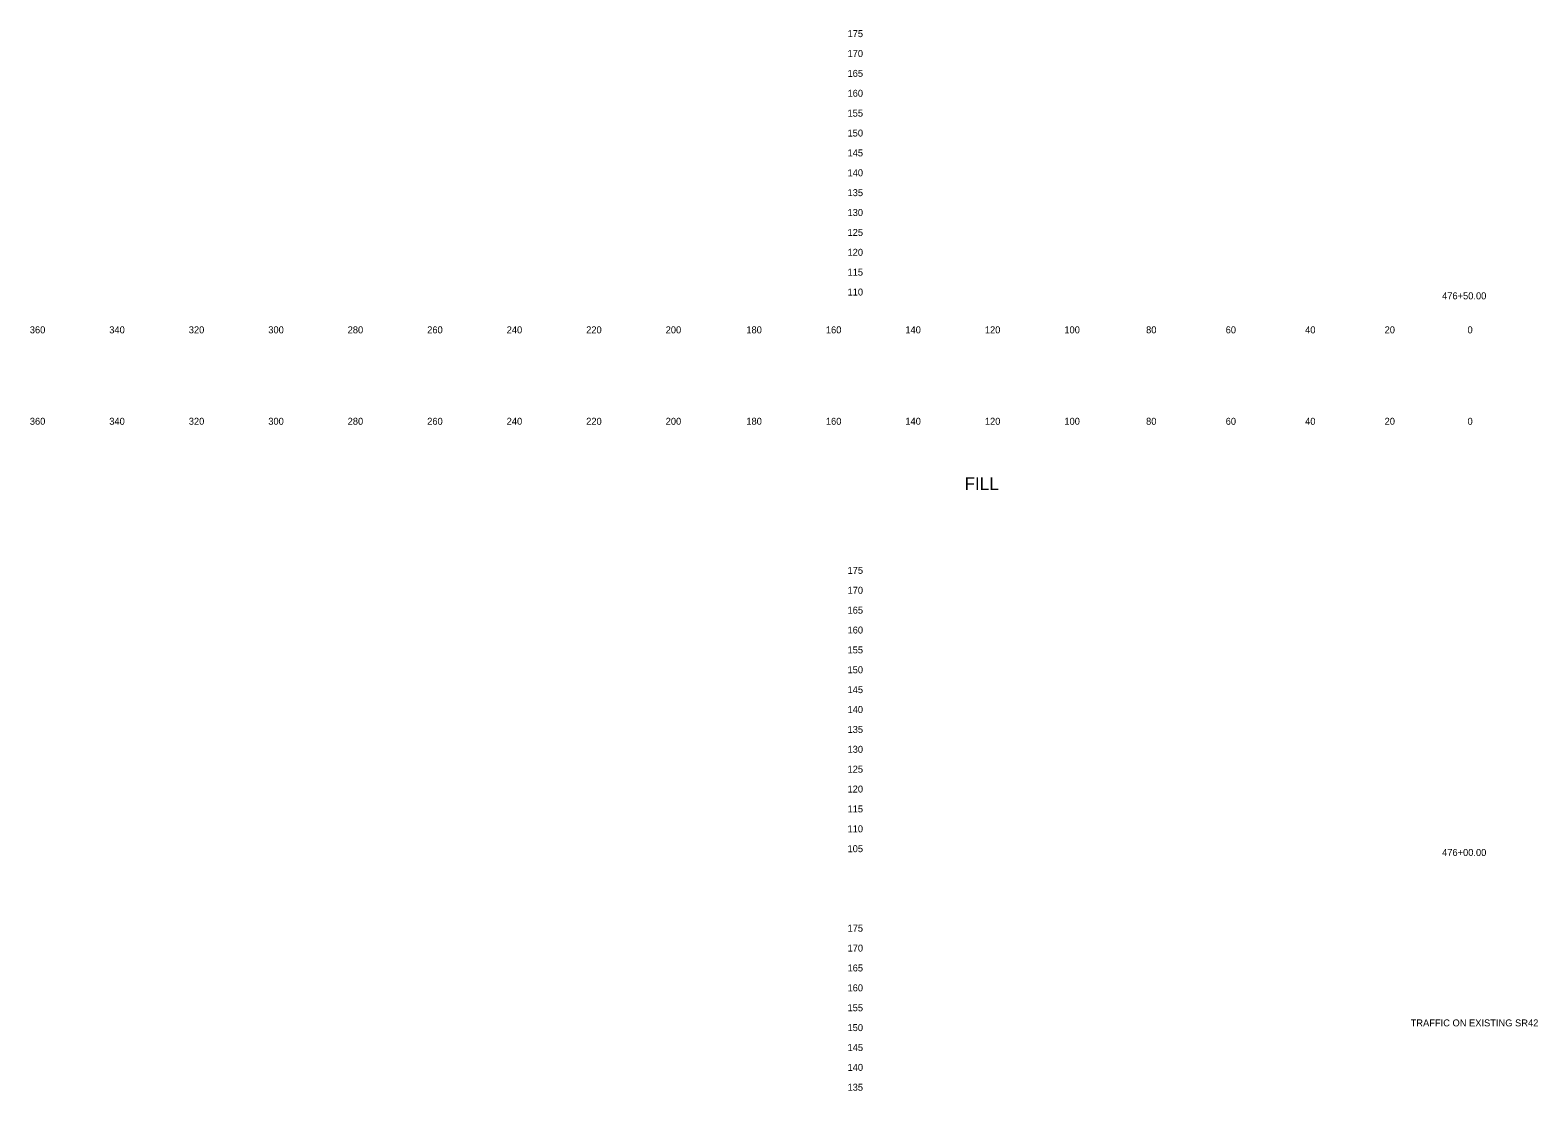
# Model space of a CAD drawing. Extents: x 21281 to 22024, y 6472 to 15198.
# Drawn here: x 21280.5 to 21659.8, y 11114.8 to 11381.6 of the extents above; entities that cross this region are included whole.
import ezdxf

# ---------------------------------------------------------------- set-up
doc = ezdxf.new("R2010")
doc.units = 0
for name, color, linetype in [('XS_SHEET_LABELS_ELEVATION', 7, 'Continuous'), ('XS_SHEET_LABELS_OFFSET', 7, 'Continuous'), ('XS_SHEET_LABELS_STATION', 7, 'Continuous')]:
    doc.layers.add(name, color=color, linetype=linetype)

msp = doc.modelspace()

# ---------------------------------------------------------------- texts
at = {"layer": 'XS_SHEET_LABELS_ELEVATION'}
for s, p in [('  175  ', (21484.84, 11379.84)), ('  170  ', (21484.84, 11374.84)), ('  165  ', (21484.84, 11369.84)), ('  160  ', (21484.84, 11364.84)), ('  155  ', (21484.84, 11359.84)), ('  150  ', (21484.84, 11354.84)), ('  145  ', (21484.84, 11349.84)), ('  140  ', (21484.84, 11344.84)), ('  135  ', (21484.84, 11339.84)), ('  130  ', (21484.84, 11334.84)), ('  125  ', (21484.84, 11329.84)), ('  120  ', (21484.84, 11324.84)), ('  115  ', (21484.84, 11319.84)), ('  110  ', (21484.84, 11314.84)), ('  175  ', (21484.84, 11244.84)), ('  170  ', (21484.84, 11239.84)), ('  165  ', (21484.84, 11234.84)), ('  160  ', (21484.84, 11229.84)), ('  155  ', (21484.84, 11224.84)), ('  150  ', (21484.84, 11219.84)), ('  145  ', (21484.84, 11214.84)), ('  140  ', (21484.84, 11209.84)), ('  135  ', (21484.84, 11204.84)), ('  130  ', (21484.84, 11199.84)), ('  125  ', (21484.84, 11194.84)), ('  120  ', (21484.84, 11189.84)), ('  115  ', (21484.84, 11184.84)), ('  110  ', (21484.84, 11179.84)), ('  105  ', (21484.84, 11174.84)), ('  175  ', (21484.84, 11154.84)), ('  170  ', (21484.84, 11149.84)), ('  165  ', (21484.84, 11144.84)), ('  160  ', (21484.84, 11139.84)), ('  155  ', (21484.84, 11134.84)), ('  150  ', (21484.84, 11129.84)), ('  145  ', (21484.84, 11124.84)), ('  140  ', (21484.84, 11119.84)), ('  135  ', (21484.84, 11114.84))]:
    msp.add_text(s, height=1.75, dxfattribs=at).set_placement(p)
at = {"layer": 'XS_SHEET_LABELS_OFFSET'}
for s, height, p in [('  360  ', 1.75, (21279.14, 11305.34)), ('  340  ', 1.75, (21299.13, 11305.34)), ('  320  ', 1.75, (21319.13, 11305.34)), ('  300  ', 1.75, (21339.13, 11305.34)), ('  280  ', 1.75, (21359.1, 11305.34)), ('  260  ', 1.75, (21379.11, 11305.34)), ('  240  ', 1.75, (21399.1, 11305.34)), ('  220  ', 1.75, (21419.1, 11305.34)), ('  200  ', 1.75, (21439.1, 11305.34)), ('  180  ', 1.75, (21459.39, 11305.34)), ('  160  ', 1.75, (21479.4, 11305.34)), ('  140  ', 1.75, (21499.39, 11305.34)), ('  120  ', 1.75, (21519.39, 11305.34)), ('  100  ', 1.75, (21539.39, 11305.34)), ('  80  ', 1.75, (21559.95, 11305.34)), ('  60  ', 1.75, (21579.97, 11305.34)), ('  40  ', 1.75, (21599.95, 11305.34)), ('  20  ', 1.75, (21619.95, 11305.34)), ('  0  ', 1.75, (21640.81, 11305.34)), ('  0  ', 1.75, (21640.81, 11305.34)), ('  360  ', 1.75, (21279.14, 11282.34)), ('  340  ', 1.75, (21299.13, 11282.34)), ('  320  ', 1.75, (21319.13, 11282.34)), ('  300  ', 1.75, (21339.13, 11282.34)), ('  280  ', 1.75, (21359.1, 11282.34)), ('  260  ', 1.75, (21379.11, 11282.34)), ('  240  ', 1.75, (21399.1, 11282.34)), ('  220  ', 1.75, (21419.1, 11282.34)), ('  200  ', 1.75, (21439.1, 11282.34)), ('  180  ', 1.75, (21459.39, 11282.34)), ('  160  ', 1.75, (21479.4, 11282.34)), ('  140  ', 1.75, (21499.39, 11282.34)), ('  120  ', 1.75, (21519.39, 11282.34)), ('  100  ', 1.75, (21539.39, 11282.34)), ('  80  ', 1.75, (21559.95, 11282.34)), ('  60  ', 1.75, (21579.97, 11282.34)), ('  40  ', 1.75, (21599.95, 11282.34)), ('  20  ', 1.75, (21619.95, 11282.34)), ('  0  ', 1.75, (21640.81, 11282.34)), ('  0  ', 1.75, (21640.81, 11282.34)), ('FILL', 3.222, (21515.57, 11265.93))]:
    msp.add_text(s, height=height, dxfattribs=at).set_placement(p)
at = {"layer": 'XS_SHEET_LABELS_STATION'}
for s, p in [('  476+50.00  ', (21634.41, 11313.89)), ('  476+00.00  ', (21634.41, 11173.89)), ('TRAFFIC ON EXISTING SR42', (21627.8, 11131.02))]:
    msp.add_text(s, height=1.75, dxfattribs=at).set_placement(p)

doc.saveas('drawing.dxf')
